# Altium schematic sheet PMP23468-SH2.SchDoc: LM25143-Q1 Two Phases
size 431 x 279 mm; Date: Not shown in title block; ApprovedBy: Not shown in title block; CheckedBy: Not shown in title block; Author: Not shown in title block; CompanyName: Not shown in title block; Engineer: Not shown in title block; Organization: Not shown in title block; Address1: Not shown in title block; Address2: Not shown in title block; Address3: Not shown in title block; Address4: Not shown in title block; DocumentNumber: 2; Revision: Use project parameter SCH_Rev; SheetNumber: 2; SheetTotal: 2; PageSetup: Record=PageOptions¦CenterHorizontal=True¦CenterVertical=True¦PrintScale=0.96¦XCorrection=1.00¦YCorrection=1.00¦PrintKind=0¦BorderSize=5000000¦LeftOffset=0¦BottomOffset=0¦Orientation=2¦PaperLength=1000¦PaperWidth=1000¦Scale=100¦PaperSource=7¦PrintQuality=600¦MediaType=1¦DitherType=10¦PaperKind=11" x 17"¦PrintScaleMode=1
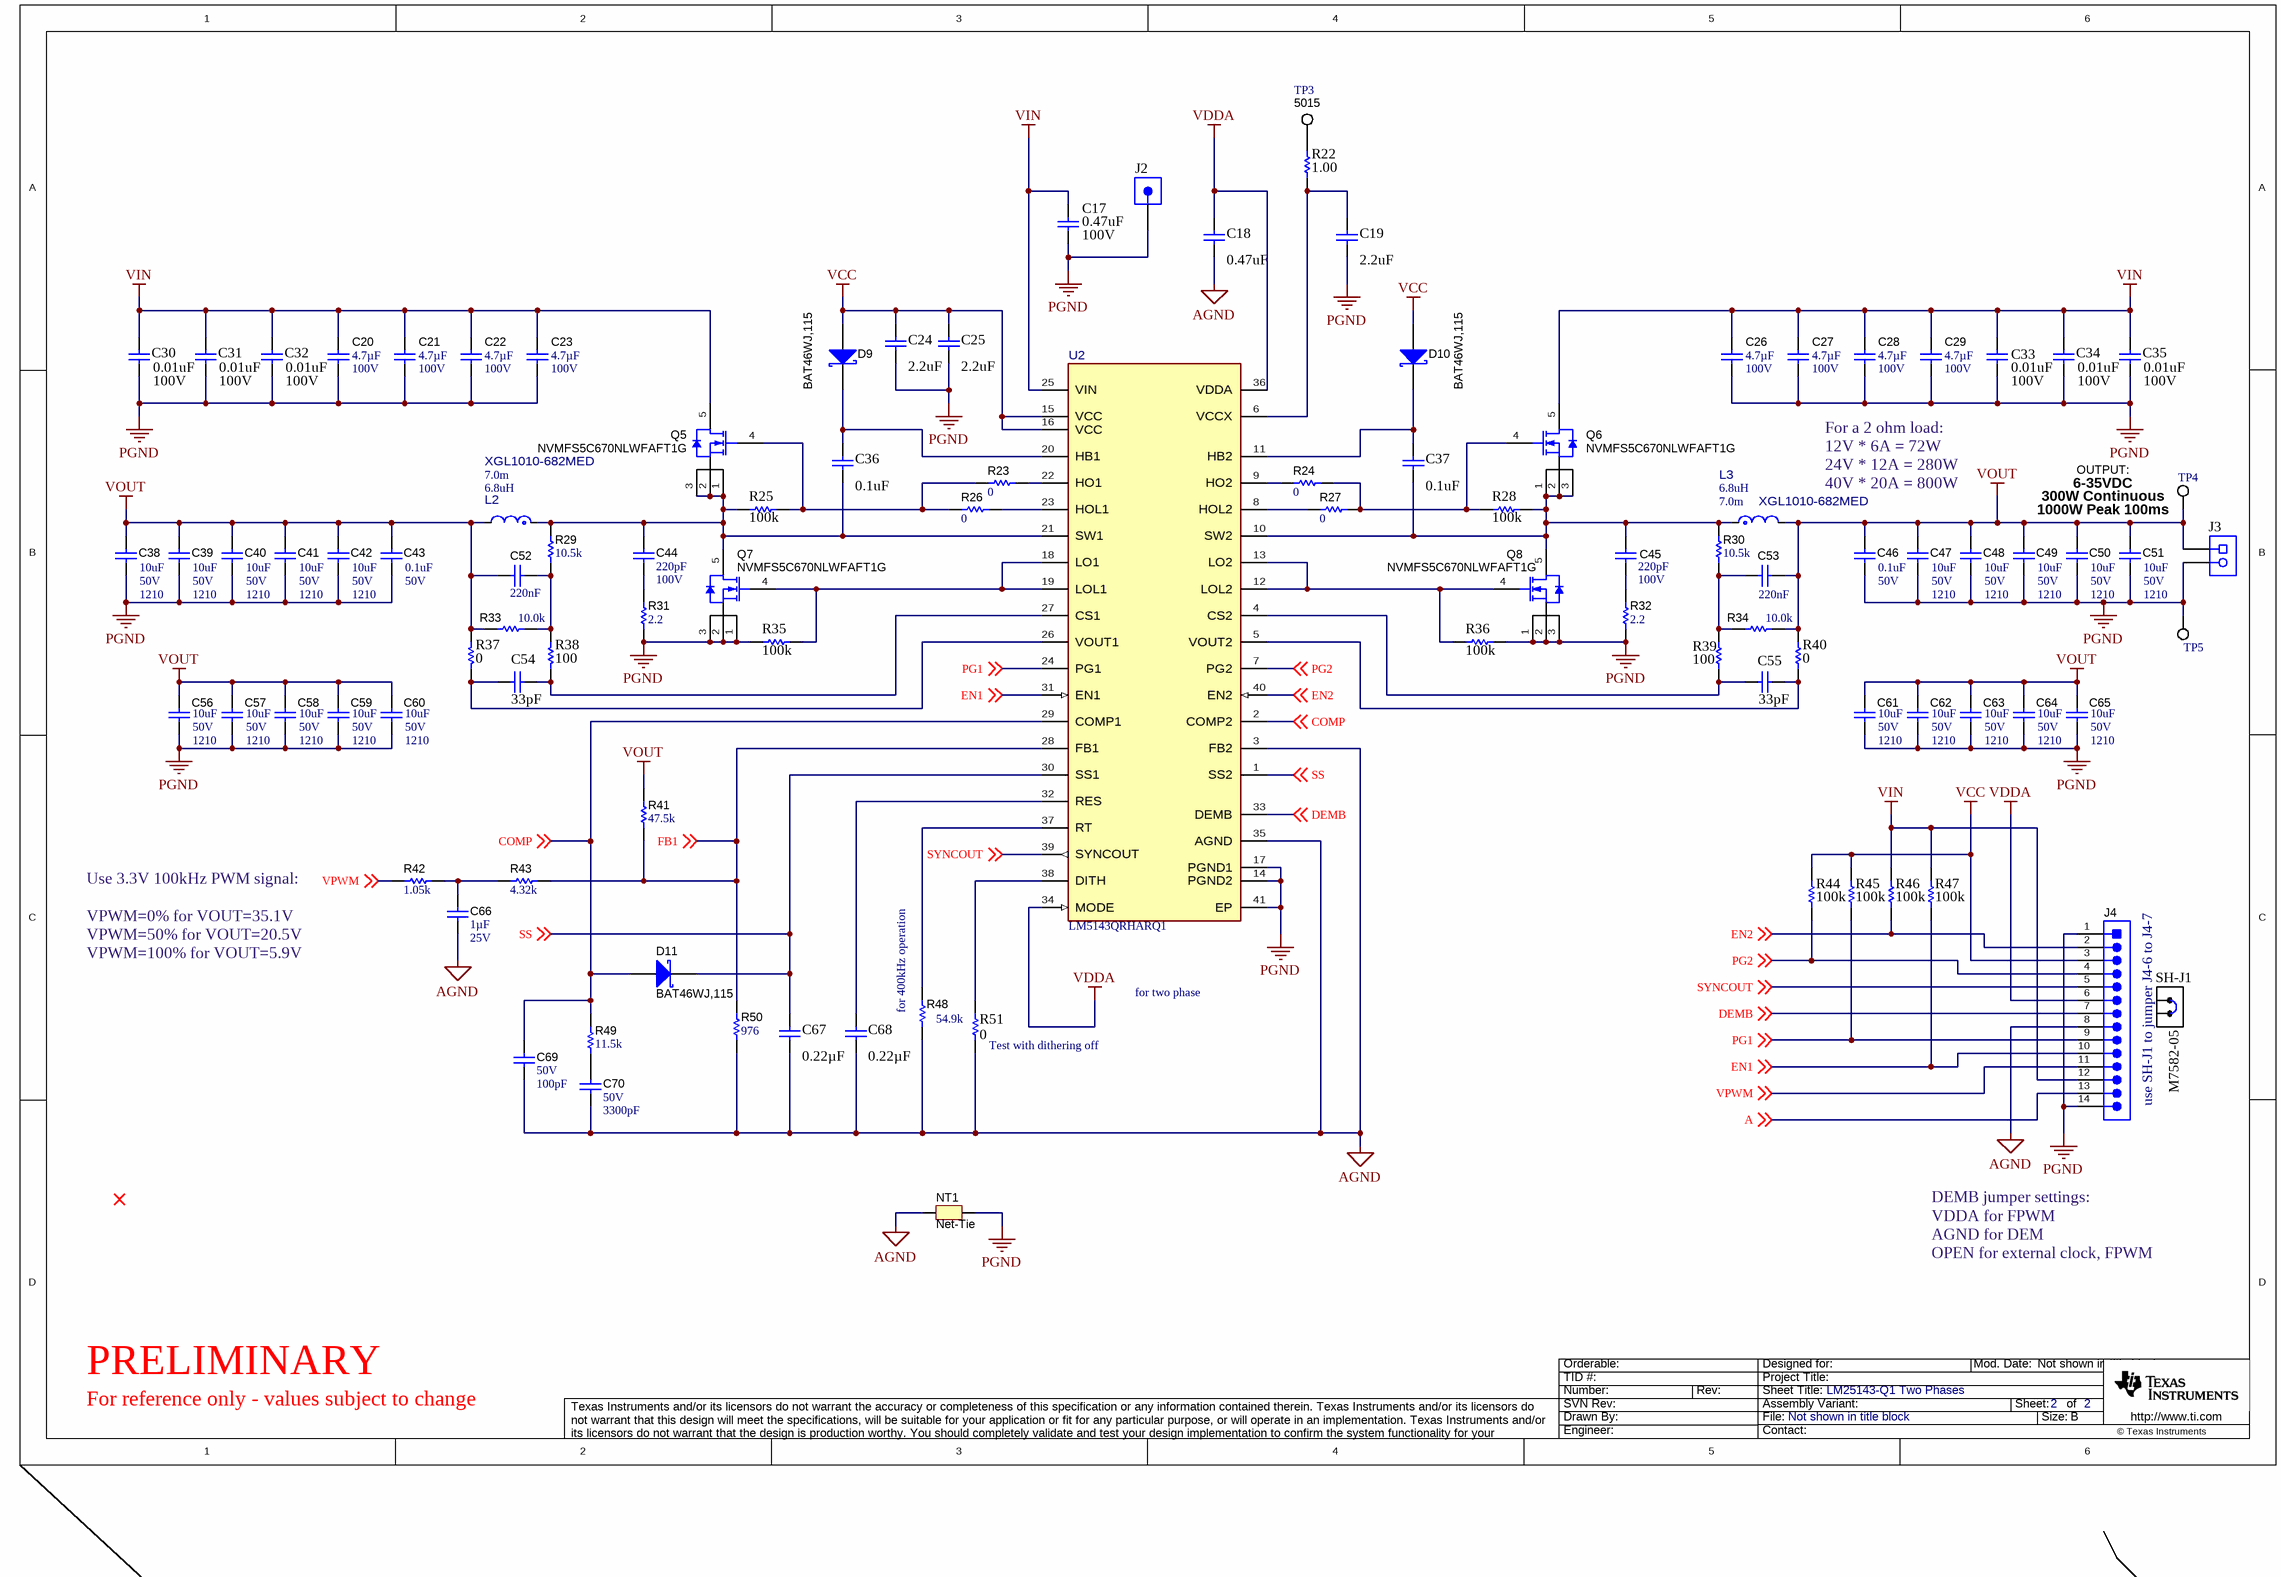
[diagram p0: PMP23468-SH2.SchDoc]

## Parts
C17  VDC_V: 100V  ValueDisplayed: 0.47uF  [0805L]  (hidden comment: GRM21BR72A474KA73L)
C18  ValueDisplayed: 0.47uF  [0603L]  (hidden comment: GCM188R71C474KA55D)
C19  ValueDisplayed: 2.2uF  [0603L]  (hidden comment: GRM188R71A225KE15D)
C20  VDC_V: 100V  ValueDisplayed: 4.7µF  [1210_220]  (hidden comment: GCM32DC72A475KE02L)
C21  VDC_V: 100V  ValueDisplayed: 4.7µF  [1210_220]  (hidden comment: GCM32DC72A475KE02L)
C22  VDC_V: 100V  ValueDisplayed: 4.7µF  [1210_220]  (hidden comment: GCM32DC72A475KE02L)
C23  VDC_V: 100V  ValueDisplayed: 4.7µF  [1210_220]  (hidden comment: GCM32DC72A475KE02L)
C24  ValueDisplayed: 2.2uF  [0603L]  (hidden comment: GRM188R71A225KE15D)
C25  ValueDisplayed: 2.2uF  [0603L]  (hidden comment: GRM188R71A225KE15D)
C26  VDC_V: 100V  ValueDisplayed: 4.7µF  [1210_220]  (hidden comment: GCM32DC72A475KE02L)
C27  VDC_V: 100V  ValueDisplayed: 4.7µF  [1210_220]  (hidden comment: GCM32DC72A475KE02L)
C28  VDC_V: 100V  ValueDisplayed: 4.7µF  [1210_220]  (hidden comment: GCM32DC72A475KE02L)
C29  VDC_V: 100V  ValueDisplayed: 4.7µF  [1210_220]  (hidden comment: GCM32DC72A475KE02L)
C30  VDC_V: 100V  ValueDisplayed: 0.01uF  [0402S]  (hidden comment: CGA2B3X7S2A103K050BB)
C31  VDC_V: 100V  ValueDisplayed: 0.01uF  [0402S]  (hidden comment: CGA2B3X7S2A103K050BB)
C32  VDC_V: 100V  ValueDisplayed: 0.01uF  [0402S]  (hidden comment: CGA2B3X7S2A103K050BB)
C33  VDC_V: 100V  ValueDisplayed: 0.01uF  [0402S]  (hidden comment: CGA2B3X7S2A103K050BB)
C34  VDC_V: 100V  ValueDisplayed: 0.01uF  [0402S]  (hidden comment: CGA2B3X7S2A103K050BB)
C35  VDC_V: 100V  ValueDisplayed: 0.01uF  [0402S]  (hidden comment: CGA2B3X7S2A103K050BB)
C36  ValueDisplayed: 0.1uF  [0603L]  (hidden comment: CGA3E2X7R1E104K080AA)
C37  ValueDisplayed: 0.1uF  [0603L]  (hidden comment: CGA3E2X7R1E104K080AA)
C38  PackageReference: 1210  VDC_V: 50V  ValueDisplayed: 10uF  [1210_270]  (hidden comment: UMJ325KB7106KMHT)
C39  PackageReference: 1210  VDC_V: 50V  ValueDisplayed: 10uF  [1210_270]  (hidden comment: UMJ325KB7106KMHT)
C40  PackageReference: 1210  VDC_V: 50V  ValueDisplayed: 10uF  [1210_270]  (hidden comment: UMJ325KB7106KMHT)
C41  PackageReference: 1210  VDC_V: 50V  ValueDisplayed: 10uF  [1210_270]  (hidden comment: UMJ325KB7106KMHT)
C42  PackageReference: 1210  VDC_V: 50V  ValueDisplayed: 10uF  [1210_270]  (hidden comment: UMJ325KB7106KMHT)
C43  Value2: 50V  ValueDisplayed: 0.1uF  [0603]  (hidden comment: CGA3E2X7R1H104K080AA)
C44  Cap_F: 220pF  VDC_V: 100V  [0603_HV]  (hidden comment: 06031C221KAT2A)
C45  Cap_F: 220pF  VDC_V: 100V  [0603_HV]  (hidden comment: 06031C221KAT2A)
C46  Value2: 50V  ValueDisplayed: 0.1uF  [0603]  (hidden comment: CGA3E2X7R1H104K080AA)
C47  PackageReference: 1210  VDC_V: 50V  ValueDisplayed: 10uF  [1210_270]  (hidden comment: UMJ325KB7106KMHT)
C48  PackageReference: 1210  VDC_V: 50V  ValueDisplayed: 10uF  [1210_270]  (hidden comment: UMJ325KB7106KMHT)
C49  PackageReference: 1210  VDC_V: 50V  ValueDisplayed: 10uF  [1210_270]  (hidden comment: UMJ325KB7106KMHT)
C50  PackageReference: 1210  VDC_V: 50V  ValueDisplayed: 10uF  [1210_270]  (hidden comment: UMJ325KB7106KMHT)
C51  PackageReference: 1210  VDC_V: 50V  ValueDisplayed: 10uF  [1210_270]  (hidden comment: UMJ325KB7106KMHT)
C52  Cap_F: 220nF  [0603]  (hidden comment: CGA3E3X7R1H224K080AB)
C53  Cap_F: 220nF  [0603]  (hidden comment: CGA3E3X7R1H224K080AB)
C54  ValueDisplayed: 33pF  [0603L]  (hidden comment: 06031A330JAT2A)
C55  ValueDisplayed: 33pF  [0603L]  (hidden comment: 06031A330JAT2A)
C56  PackageReference: 1210  VDC_V: 50V  ValueDisplayed: 10uF  [1210_270]  (hidden comment: UMJ325KB7106KMHT)
C57  PackageReference: 1210  VDC_V: 50V  ValueDisplayed: 10uF  [1210_270]  (hidden comment: UMJ325KB7106KMHT)
C58  PackageReference: 1210  VDC_V: 50V  ValueDisplayed: 10uF  [1210_270]  (hidden comment: UMJ325KB7106KMHT)
C59  PackageReference: 1210  VDC_V: 50V  ValueDisplayed: 10uF  [1210_270]  (hidden comment: UMJ325KB7106KMHT)
C60  PackageReference: 1210  VDC_V: 50V  ValueDisplayed: 10uF  [1210_270]  (hidden comment: UMJ325KB7106KMHT)
C61  PackageReference: 1210  VDC_V: 50V  ValueDisplayed: 10uF  [1210_270]  (hidden comment: UMJ325KB7106KMHT)
C62  PackageReference: 1210  VDC_V: 50V  ValueDisplayed: 10uF  [1210_270]  (hidden comment: UMJ325KB7106KMHT)
C63  PackageReference: 1210  VDC_V: 50V  ValueDisplayed: 10uF  [1210_270]  (hidden comment: UMJ325KB7106KMHT)
C64  PackageReference: 1210  VDC_V: 50V  ValueDisplayed: 10uF  [1210_270]  (hidden comment: UMJ325KB7106KMHT)
C65  PackageReference: 1210  VDC_V: 50V  ValueDisplayed: 10uF  [1210_270]  (hidden comment: UMJ325KB7106KMHT)
C66  Cap_F: 1µF  VDC_V: 25V  [0603S]  (hidden comment: CGA3E1X7R1E105K080AC)
C67  ValueDisplayed: 0.22µF  [0603L]  (hidden comment: CL10B224KO8VPNC)
C68  ValueDisplayed: 0.22µF  [0603L]  (hidden comment: CL10B224KO8VPNC)
C69  VDC_V: 50V  ValueDisplayed: 100pF  [0603]  (hidden comment: CGA3E2NP01H101J080AA)
C70  VDC_V: 50V  ValueDisplayed: 3300pF  [0603]  (hidden comment: GRM1885C1H332JA01D)
D9  BAT46WJ,115  [SOD-323F]
D10  BAT46WJ,115  [SOD-323F]
D11  BAT46WJ,115  [SOD-323F]
J2  1040  [CONN_1040]  (value not drawn)
J3  EM292902-UL  [Eaton_EM292902]  (value not drawn)
J4  TSW-114-07-G-S  [TSW-114-07-G-S]  (value not drawn)
L2  XGL1010-682MED  value 6.8uH  DCR_ohm: 7.0m  [FP-XGL1010-103MED_SMT_IND_10MM0_11MM3-MFG]
L3  XGL1010-682MED  value 6.8uH  DCR_ohm: 7.0m  [FP-XGL1010-103MED_SMT_IND_10MM0_11MM3-MFG]
NT1  Net-Tie  [Net-Tie_10mil]  (net tie, no BOM)
Q5  NVMFS5C670NLWFAFT1G  [SO-8FL]
Q6  NVMFS5C670NLWFAFT1G  [SO-8FL]
Q7  NVMFS5C670NLWFAFT1G  [SO-8FL]
Q8  NVMFS5C670NLWFAFT1G  [SO-8FL]
R22  ValueDisplayed: 1.00  [0603L]  (hidden comment: RC0603FR-071RL)
R23  ValueDisplayed: 0  [0402L]  (hidden comment: ERJ-2GE0R00X)
R24  ValueDisplayed: 0  [0402L]  (hidden comment: ERJ-2GE0R00X)
R25  ValueDisplayed: 100k  [0603L]  (hidden comment: CRCW0603100KFKEA)
R26  ValueDisplayed: 0  [0402L]  (hidden comment: ERJ-2GE0R00X)
R27  ValueDisplayed: 0  [0402L]  (hidden comment: ERJ-2GE0R00X)
R28  ValueDisplayed: 100k  [0603L]  (hidden comment: CRCW0603100KFKEA)
R29  ValueDisplayed: 10.5k  [0603]  (hidden comment: CRCW060310K5FKEA)
R30  ValueDisplayed: 10.5k  [0603]  (hidden comment: CRCW060310K5FKEA)
R31  ValueDisplayed: 2.2  [0805_HV]  (hidden comment: ERJ-6GEYJ2R2V)
R32  ValueDisplayed: 2.2  [0805_HV]  (hidden comment: ERJ-6GEYJ2R2V)
R33  ValueDisplayed: 10.0k  [0603]  (hidden comment: RMCF0603FT10K0)
R34  ValueDisplayed: 10.0k  [0603]  (hidden comment: RMCF0603FT10K0)
R35  ValueDisplayed: 100k  [0603L]  (hidden comment: CRCW0603100KFKEA)
R36  ValueDisplayed: 100k  [0603L]  (hidden comment: CRCW0603100KFKEA)
R37  ValueDisplayed: 0  [0603L]  (hidden comment: CRCW06030000Z0EA)
R38  ValueDisplayed: 100  [0603L]  (hidden comment: CRCW0603100RFKEA)
R39  ValueDisplayed: 100  [0603L]  (hidden comment: CRCW0603100RFKEA)
R40  ValueDisplayed: 0  [0603L]  (hidden comment: CRCW06030000Z0EA)
R41  ValueDisplayed: 47.5k  [0603L]  (hidden comment: CRCW060347K5FKEA)
R42  ValueDisplayed: 1.05k  [0603L]  (hidden comment: CRCW06031K05FKEA)
R43  ValueDisplayed: 4.32k  [0603L]  (hidden comment: CRCW06034K32FKEA)
R44  ValueDisplayed: 100k  [0603L]  (hidden comment: CRCW0603100KFKEA)
R45  ValueDisplayed: 100k  [0603L]  (hidden comment: CRCW0603100KFKEA)
R46  ValueDisplayed: 100k  [0603L]  (hidden comment: CRCW0603100KFKEA)
R47  ValueDisplayed: 100k  [0603L]  (hidden comment: CRCW0603100KFKEA)
R48  ValueDisplayed: 54.9k  [0603L]  (hidden comment: CRCW060354K9FKEA)
R49  ValueDisplayed: 11.5k  [0603]  (hidden comment: CRCW060311K5FKEA)
R50  ValueDisplayed: 976  [0603]  (hidden comment: CRCW0603976RFKEA)
R51  ValueDisplayed: 0  [0603L]  (hidden comment: CRCW06030000Z0EA)
SH-J1  M7582-05  [Harwin_M7582-05]
TP3  5015  [Testpoint_Keystone_Miniature]
TP4  5015  [Testpoint_Keystone_Miniature]  (value not drawn)
TP5  5015  [Testpoint_Keystone_Miniature]  (value not drawn)
U2  LM5143QRHARQ1  [RHA0040N-MFG]

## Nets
AGND: C18.1 C66.1 C67.2 C68.2 C69.2 C70.2 J4.8 NT1.1 R48.1 R50.1 R51.2 U2.3(FB2) U2.35(AGND)
PGND: C17.1 C19.2 C20.2 C21.2 C22.2 C23.2 C24.2 C25.2 C26.2 C27.2 C28.2 C29.2 C30.2 C31.2 C32.2 C33.2 C34.2 C35.2 C38.2 C39.2 C40.2 C41.2 C42.2 C43.2 C46.2 C47.2 C48.2 C49.2 C50.2 C51.2 C56.2 C57.2 C58.2 C59.2 C60.2 C61.2 C62.2 C63.2 C64.2 C65.2 J2.1 J3.2 J4.1 J4.14 NT1.2 Q7.1(S) Q7.2(S) Q7.3(S) Q8.1(S) Q8.2(S) Q8.3(S) R31.1 R32.1 R35.2 R36.1 TP5.1 U2.14(PGND2) U2.17(PGND1) U2.41(EP)
VCC: C24.1 C25.1 D9.2(A) D10.2(A) J4.3 R44.2 R45.2 U2.15(VCC) U2.16(VCC)
VDDA: C18.2 J4.6 U2.34(MODE) U2.36(VDDA)
VIN: C17.2 C20.1 C21.1 C22.1 C23.1 C26.1 C27.1 C28.1 C29.1 C30.1 C31.1 C32.1 C33.1 C34.1 C35.1 J4.12 Q5.5(D) Q6.5(D) R46.2 R47.2 U2.25(VIN)
VOUT: C38.1 C39.1 C40.1 C41.1 C42.1 C43.1 C46.1 C47.1 C48.1 C49.1 C50.1 C51.1 C52.2 C53.1 C56.1 C57.1 C58.1 C59.1 C60.1 C61.1 C62.1 C63.1 C64.1 C65.1 J3.1 L2.2 L3.2 R33.1 R34.2 R37.2 R40.2 R41.2 TP4.1
A: J4.13 ; off-sheet A
COMP: C69.1 D11.2(A) R49.2 U2.2(COMP2) U2.29(COMP1) ; off-sheet COMP
DEMB: J4.7 U2.33(DEMB) ; off-sheet DEMB
EN1: J4.10 R47.1 U2.31(EN1) ; off-sheet EN1
EN2: J4.2 R46.1 U2.40(EN2) ; off-sheet EN2
FB1: R41.1 R43.1 R50.2 U2.28(FB1) ; off-sheet FB1
PG1: J4.9 R45.1 U2.24(PG1) ; off-sheet PG1
PG2: J4.4 R44.1 U2.7(PG2) ; off-sheet PG2
SS: C67.1 D11.1(K) U2.1(SS2) U2.30(SS1) ; off-sheet SS
SYNCOUT: J4.5 U2.39(SYNCOUT) ; off-sheet SYNCOUT
VPWM: J4.11 R42.2 ; off-sheet VPWM
NetC19_1: C19.1 R22.1 U2.6(VCCX)
NetC36_1: C36.1 C44.1 L2.1 Q5.1(S) Q5.2(S) Q5.3(S) Q7.5(D) R25.2 R29.2 U2.21(SW1)
NetC36_2: C36.2 D9.1(K) U2.20(HB1)
NetC37_1: C37.1 C45.1 L3.1 Q6.1(S) Q6.2(S) Q6.3(S) Q8.5(D) R28.1 R30.1 U2.10(SW2)
NetC37_2: C37.2 D10.1(K) U2.11(HB2)
NetC44_2: C44.2 R31.2
NetC45_2: C45.2 R32.2
NetC52_1: C52.1 R29.1 R33.2 R38.2
NetC53_2: C53.2 R30.2 R34.1 R39.2
NetC54_1: C54.1 R37.1 U2.26(VOUT1)
NetC54_2: C54.2 R38.1 U2.27(CS1)
NetC55_1: C55.1 R40.1 U2.5(VOUT2)
NetC55_2: C55.2 R39.1 U2.4(CS2)
NetC66_2: C66.2 R42.1 R43.2
NetC68_1: C68.1 U2.32(RES)
NetC70_1: C70.1 R49.1
NetQ5_4: Q5.4(G) R23.1 R25.1 R26.1
NetQ6_4: Q6.4(G) R24.2 R27.2 R28.2
NetQ7_4: Q7.4(G) R35.1 U2.18(LO1) U2.19(LOL1)
NetQ8_4: Q8.4(G) R36.2 U2.12(LOL2) U2.13(LO2)
NetR22_2: R22.2 TP3.1
NetR23_2: R23.2 U2.22(HO1)
NetR24_1: R24.1 U2.9(HO2)
NetR26_2: R26.2 U2.23(HOL1)
NetR27_1: R27.1 U2.8(HOL2)
NetR48_2: R48.2 U2.37(RT)
NetR51_1: R51.1 U2.38(DITH)

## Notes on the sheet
- For a 2 ohm load:
  12V * 6A = 72W
  24V * 12A = 280W
  40V * 20A = 800W
- 6-35VDC
- (near TP4) 300W Continuous
- OUTPUT:
- 1000W Peak 100ms
- Use 3.3V 100kHz PWM signal:
  VPWM=0% for VOUT=35.1V
  VPWM=50% for VOUT=20.5V
  VPWM=100% for VOUT=5.9V
- (near R48) for 400kHz operation
- for two phase
- (near R51) Test with dithering off
- (near SH-J1) use SH-J1 to jumper J4-6 to J4-7
- DEMB jumper settings:
  VDDA for FPWM
  AGND for DEM
  OPEN for external clock, FPWM
- PRELIMINARY
- For reference only - values subject to change

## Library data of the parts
C17 = CMP-0008374-2: CAP, CERM, 0.47 uF, 100 V, +/- 10%, X7R, 0805; Manufacturer: MuRata; TaMin_C: -55°C; Polarized: N; SizeAreaWB_mm2: 6.75; Value1: Unknown; U/M: EA; Value: 0.47uF; TaMax_C: 125°C; SizeZ_mm: 1.45; SizeX_mm: 2; SizeY_mm: 1.25; Cap_Case: 0805; SizeArea_mm2: 2.5; CompType: Capacitor; Cap_F: 470nF; AEC Category: Q200
C18 = CMP-0007138-4: CAP, CERM, 0.47 uF, 16 V, +/- 10%, X7R, AEC-Q200 Grade 1, 0603; Manufacturer: MuRata; TaMin_C: -55°C; Polarized: N; SizeAreaWB_mm2: 4.68; Value1: Unknown; U/M: EA; Value: 0.47uF; TaMax_C: 125°C; SizeZ_mm: 1; SizeX_mm: 1.6; SizeY_mm: 0.8; Cap_Case: 0603; Value2: 16V; SizeArea_mm2: 1.28; CompType: Capacitor; AEC Qualified: Y; Cap_F: 470nF; AEC Category: Q200
C19 = CMP-0007370-4: CAP, CERM, 2.2 uF, 10 V, +/- 10%, X7R, 0603; Manufacturer: MuRata; TaMin_C: -55°C; Polarized: N; SizeAreaWB_mm2: 4.68; Value1: 0.009 ohm; U/M: EA; Value: 2.2uF; TaMax_C: 125°C; SizeZ_mm: 1; SizeX_mm: 1.6; SizeY_mm: 0.8; Cap_Case: 0603; Value2: 10V; SizeArea_mm2: 1.28; CompType: Capacitor; Cap_F: 2.2µF; AEC Category: Q200; ESR_ohm: 9m
C20-C23 C26-C29 = CMP-0082268-1: CAP, CERM, 4.7 µF, 100 V,+/- 10%, X7S, AEC-Q200 Grade 1, 1210; Manufacturer: MuRata; TaMin_C: -55°C; ESR_ohm: 1m; Polarized: N; SizeAreaWB_mm2: 14.7; Value1: 0.001 ohm; U/M: EA; Value: 4.7uF; TaMax_C: 125°C; SizeZ_mm: 2.2; SizeX_mm: 3.2; SizeY_mm: 2.5; Cap_Case: 1210; SizeArea_mm2: 8; AEC Qualified: Y; IRMS_A: 6A; AEC Grade: 1; AEC Category: Q200
C24 C25 = CMP-0007370-4: CAP, CERM, 2.2 uF, 10 V, +/- 10%, X7R, 0603; Manufacturer: MuRata; TaMin_C: -55°C; ESR_ohm: 9m; Polarized: N; SizeAreaWB_mm2: 4.68; Value1: 0.009 ohm; U/M: EA; Value: 2.2uF; TaMax_C: 125°C; SizeZ_mm: 1; SizeX_mm: 1.6; SizeY_mm: 0.8; Cap_Case: 0603; Value2: 10V; SizeArea_mm2: 1.28; CompType: Capacitor; Cap_F: 2.2µF; AEC Category: Q200
C30-C35 = CMP-0006333-2: CAP, CERM, 0.01 uF, 100 V, +/- 10%, X7S, AEC-Q200 Grade 1, 0402; Manufacturer: TDK; TaMin_C: -55°C; ESR_ohm: 0.4102; Polarized: N; SizeAreaWB_mm2: 3; Value1: 0.410191 ohm; U/M: EA; Value: 0.01uF; TaMax_C: 125°C; SizeZ_mm: 0.6; SizeX_mm: 1; SizeY_mm: 0.5; Cap_Case: 0402; AEC Qualified: Y; Cap_F: 10nF; IRMS_A: 291.729mA; AEC Category: Q200
C36 C37 = CMP-0007077-5: CAP, CERM, 0.1 uF, 25 V, +/- 10%, X7R, AEC-Q200 Grade 1, 0603; Manufacturer: TDK; TaMin_C: -55°C; Polarized: N; SizeAreaWB_mm2: 4.68; Value1: Unknown; U/M: EA; Value: 0.1uF; TaMax_C: 125°C; SizeZ_mm: 1; SizeX_mm: 1.6; SizeY_mm: 0.8; Cap_Case: 0603; Value2: 25V; SizeArea_mm2: 1.28; AEC Qualified: Y; Cap_F: 100nF; AEC Category: Q200
C38-C42 C47-C51 C56-C65 = CMP-0009257-2: CAP, CERM, 10 uF, 50 V, +/- 10%, X7R, AEC-Q200 Grade 1, 1210; Manufacturer: Taiyo Yuden; TaMin_C: -55°C; Polarized: N; SizeAreaWB_mm2: 14.7; Value1: Unknown; Value: 10uF; TaMax_C: 125°C; SizeZ_mm: 2.7; SizeX_mm: 3.2; SizeY_mm: 2.5; SizeArea_mm2: 8; AEC Qualified: Y; Cap_F: 10µF; AEC Grade: 1; AEC Category: Q200; U/M: EA
C43 C46 = CMP-0007078-4: CAP, CERM, 0.1 uF, 50 V, +/- 10%, X7R, AEC-Q200 Grade 1, 0603; Manufacturer: TDK; TaMin_C: -55°C; Polarized: N; SizeAreaWB_mm2: 4.68; Value1: 0.0296 ohm; U/M: EA; Value: 0.1uF; TaMax_C: 125°C; SizeZ_mm: 1; SizeX_mm: 1.6; SizeY_mm: 0.8; SizeArea_mm2: 1.28; AEC Qualified: Y; Cap_F: 100nF; AEC Category: Q200; ESR_ohm: 29.6m; IRMS_A: 971.99mA
C44 C45 = CMP-0006735-5: CAP, CERM, 220 pF, 100 V, +/- 10%, X7R, 0603; Manufacturer: AVX; TaMin_C: -55°C; ESR_ohm: 0.579; Polarized: N; SizeAreaWB_mm2: 4.68; Value1: 0.579 ohm; U/M: EA; Value: 220pF; TaMax_C: 125°C; SizeZ_mm: 1; SizeX_mm: 1.6; SizeY_mm: 0.8; Cap_Case: 0603; SizeArea_mm2: 1.28; AEC Category: Q200
C52 C53 = CMP-0007094-5: CAP, CERM, 0.22 uF, 50 V, +/- 10%, X7R, AEC-Q200 Grade 1, 0603; Manufacturer: TDK; TaMin_C: -55°C; ESR_ohm: 21.699m; Polarized: N; SizeAreaWB_mm2: 4.68; Value1: 0.021699 ohm; U/M: EA; Value: 0.22uF; TaMax_C: 125°C; SizeZ_mm: 1; SizeX_mm: 1.6; SizeY_mm: 0.8; Value2: 50V; SizeArea_mm2: 1.28; AEC Qualified: Y; IRMS_A: 1.125A; AEC Category: Q200
C54 C55 = CMP-0006722-4: CAP, CERM, 33 pF, 100 V, +/- 5%, C0G/NP0, 0603; Manufacturer: AVX; TaMin_C: -55°C; ESR_ohm: 2.09d; Polarized: N; SizeAreaWB_mm2: 4.68; Value1: 0.209 ohm; U/M: EA; Value: 33pF; TaMax_C: 125°C; SizeZ_mm: 1; SizeX_mm: 1.6; SizeY_mm: 0.8; Cap_Case: 0603; Value2: 100V; SizeArea_mm2: 1.28; CompType: Capacitor; AEC Category: Q200
C66 = CMP-0076705-3: CAP, CERM, 1 µF, 25 V,+/- 10%, X7R, AEC-Q200 Grade 1, 0603; Manufacturer: TDK; SizeAreaWB_mm2: 4.68; SizeArea_mm2: 1.28; AEC Qualified: Y; AEC Category: Q200; Value: 1uF; TaMax_C: 125°C; SizeZ_mm: 1.0; AEC Grade: 1; Polarized: N; TaMin_C: -55°C; SizeY_mm: 0.8; U/M: EA; SizeX_mm: 1.6; Cap_Case: 1.6x0.8x0.8mm
C67 C68 = CMP-0080102-1: CAP, CERM, 0.22 µF, 16 V,+/- 10%, X7R, AEC-Q200 Grade 1, 0603; Manufacturer: Samsung; TaMin_C: -55°C; Polarized: N; SizeAreaWB_mm2: 4.68; U/M: EA; Value: 0.22uF; TaMax_C: 125°C; SizeZ_mm: 1; SizeX_mm: 1.6; SizeY_mm: 0.8; Cap_Case: 0603; Value2: 16V; SizeArea_mm2: 1.28; CompType: Capacitor; AEC Qualified: Y; Cap_F: 220nF; AEC Category: Q200
C69 = CMP-0007075-4: CAP, CERM, 100 pF, 50 V, +/- 5%, C0G/NP0, AEC-Q200 Grade 0, 0603; Manufacturer: TDK; TaMin_C: -55°C; Polarized: N; SizeAreaWB_mm2: 4.68; Value1: Unknown; U/M: EA; Value: 100pF; TaMax_C: 150°C; SizeZ_mm: 1; SizeX_mm: 1.6; SizeY_mm: 0.8; SizeArea_mm2: 1.28; AEC Qualified: Y; AEC Grade: 0; AEC Category: Q200
C70 = CMP-0007210-4: CAP, CERM, 3300 pF, 50 V, +/- 5%, C0G/NP0, 0603; Manufacturer: MuRata; TaMin_C: -55°C; Polarized: N; SizeAreaWB_mm2: 4.68; Value1: Unknown; U/M: EA; Value: 3300pF; TaMax_C: 125°C; SizeZ_mm: 1; SizeX_mm: 1.6; SizeY_mm: 0.8; SizeArea_mm2: 1.28; Cap_F: 3.3nF; AEC Category: Q200
D9-D11 = CMP-0076946-2: Diode, Schottky, 100 V, 0.25 A, SOD-323F; Manufacturer: Nexperia; SizeAreaWB_mm2: 7.875; Value2: 0.85V; SizeX_mm: 2.5; Green_REACh: Incomplete; SizeArea_mm2: 3.125; Vf_V: 850mV; Green_Lifecycle: Not Set; Vr_V: 100V; TJmax_C: 150°C; Value1: 0.25A; Io_A: 250mA; SizeZ_mm: 0.8; Value: 100V; AEC Category: Q101; SizeY_mm: 1.25
J2 = CMP-0055161-1: TEST POINT SLOTTED .118", TH; Manufacturer: Keystone; CNHeader: FALSE; Green_Lifecycle: Active; Green_REACh: Passed; CT: TRUE
J3 = CMP-0077513-2: Terminal Block, 10.16mm, 2x1, Tin, R/A, TH; Manufacturer: Eaton; Pitch_mm: 10.16; Gender: Female; Voltage_V: 300V; Current_A: 65A; Cert_CULUS: Y; Row_Count: 1
J4 = CMP-0075428-1: Header, 100mil, 14x1, Gold, TH; Manufacturer: Samtec; Pitch_mm: 2.54; Cert_VDE: N; Gender: Male; Cert_CSA: Y; Current_A: 6.3A; Voltage_V: 550V; CT: False; Row_Count: 1; CNHeader: True; Green_Lifecycle: Active; Green_REACh: Passed
L2 L3 = CMP-0120510-1: 6.8 µH Shielded Molded Inductor 21.2 A 7.0mOhm Max Nonstandard; Manufacturer: Coilcraft; PartNumber: XGL1010-103MED; AEC Grade: Grade 1; AEC Qualified: Yes; Ind_H: 10µH; Irms: 18.2A; Isat: 8.3A; Material: Composite; SizeZ_mm: 10mm; Self Resonant Frequency: 12MHz; Shrouded: true; TaMax_C: +125°C; TaMin_C: -40°C; Test Frequency: 1MHz; Tolerance_%: 20%
NT1 = CMP-0078142-6: Single point connection between nets.
Q5 Q6 = CMP-0750168-1: MOSFET, N-CH, 60 V, 17 A, AEC-Q101, SO-8FL; Manufacturer: ON Semiconductor; Alternate Manufacturer: None; IdsMax_A: 17A; VdsMax_V: 60V; QgTyp_nC: 20; AEC Qualified: Y; Rdson45_ohm: 8.8m; Vgs_V: 20V; SizeZ_mm: 1.1; ChMode: Enhancement; SizeAreaWB_mm2: 58.2725; Value1: 0.0088 ohm; ChType: N; SizeArea_mm2: 31.6725; SizeX_mm: 6.15; SizeY_mm: 5.15; Value2: 20 nC; AEC Category: Q101; Value: 60V
Q7 Q8 = CMP-0750168-1: MOSFET, N-CH, 60 V, 17 A, AEC-Q101, SO-8FL; Manufacturer: ON Semiconductor; Alternate Manufacturer: None; AEC Qualified: Y; IdsMax_A: 17A; QgTyp_nC: 20; Rdson45_ohm: 8.8m; SizeZ_mm: 1.1; VdsMax_V: 60V; Vgs_V: 20V; ChMode: Enhancement; SizeAreaWB_mm2: 58.2725; Value1: 0.0088 ohm; ChType: N; SizeArea_mm2: 31.6725; SizeX_mm: 6.15; SizeY_mm: 5.15; Value2: 20 nC; AEC Category: Q101; Value: 60V
R22 = CMP-0022900-4: RES, 1.00, 1%, 0.1 W, 0603; Manufacturer: Yageo; Power_W: 100mW; TempCo: 200 ppm/C; Value_Code: 1R00; Value: 1.00; EIA_Code: E96; Res_ohm: 1; SizeX_mm: 1.6; SizeY_mm: 0.8; Value2: 0.1W; SizeArea_mm2: 1.28; CompType: Resistor; AEC Qualified: N; VDC_V: 75V; AEC Category: Q200; SizeAreaWB_mm2: 4.68
R23 R24 R26 R27 = CMP-0026992-3: RES, 0, 5%, 0.1 W, AEC-Q200 Grade 0, 0402; Manufacturer: Panasonic; Power_W: 100mW; TempCo: 600 ppm/C; Value_Code: 0000; Value: 0; EIA_Code: E24; SizeX_mm: 1; SizeY_mm: 0.5; SizeZ_mm: 0.6; Value2: 0.1W; AEC Qualified: Y; VDC_V: 50V; AEC Category: Q200; SizeAreaWB_mm2: 3
R25 R28 R35 R36 R44-R47 = CMP-0021990-4: RES, 100 k, 1%, 0.1 W, AEC-Q200 Grade 0, 0603; Manufacturer: Vishay-Dale; Power_W: 100mW; TempCo: 100 ppm/C; Value: 100k; EIA_Code: E96; SizeX_mm: 1.6; SizeY_mm: 0.8; SizeZ_mm: 1; Value2: 0.1W; SizeArea_mm2: 1.28; CompType: Resistor; AEC Qualified: Y; VDC_V: 75V; AEC Category: Q200; AEC Grade: 0
R29 R30 = CMP-0022000-4: RES, 10.5 k, 1%, 0.1 W, AEC-Q200 Grade 0, 0603; Manufacturer: Vishay-Dale; Power_W: 100mW; TempCo: 100 ppm/C; Value_Code: 10k5; Value: 10.5k; EIA_Code: E96; SizeX_mm: 1.6; SizeY_mm: 0.8; SizeZ_mm: 1; Value2: 0.1W; SizeArea_mm2: 1.28; AEC Qualified: Y; VDC_V: 75V; AEC Category: Q200; AEC Grade: 0
R31 R32 = CMP-0020693-3: RES, 2.2, 5%, 0.125 W, AEC-Q200 Grade 0, 0805; Manufacturer: Panasonic; Power_W: 125mW; TempCo: 600 ppm/C; Value_Code: 2R20; Value: 2.2; EIA_Code: E24; SizeX_mm: 2; SizeY_mm: 1.25; SizeZ_mm: 1.45; Value2: 0.125W; SizeArea_mm2: 2.5; AEC Qualified: Y; VDC_V: 150V; AEC Category: Q200; AEC Grade: 0; SizeAreaWB_mm2: 6.75
R33 R34 = CMP-0023341-3: RES, 10.0 k, 1%, 0.1 W, AEC-Q200 Grade 0, 0603; Manufacturer: Stackpole Electronics Inc; Power_W: 100mW; TempCo: 100 ppm/C; Value_Code: 10k0; U/M: EA; Value: 10.0k; EIA_Code: E96; Res_ohm: 10k; SizeX_mm: 1.6; SizeY_mm: 0.8; SizeZ_mm: 1; Value2: 0.1W; SizeArea_mm2: 1.28; AEC Qualified: Y; VDC_V: 75V; AEC Grade: 0; AEC Category: Q200
R37 R40 = CMP-0025697-4: RES, 0, 5%, 0.1 W, AEC-Q200 Grade 0, 0603; Manufacturer: Vishay-Dale; Power_W: 100mW; TempCo: 200 ppm/C; Value_Code: 0000; Value: 0; EIA_Code: E24; SizeX_mm: 1.6; SizeY_mm: 0.8; SizeZ_mm: 1; Value2: 0.1W; SizeArea_mm2: 1.28; CompType: Resistor; AEC Qualified: Y; VDC_V: 75V; AEC Category: Q200
R38 R39 = CMP-0021991-4: RES, 100, 1%, 0.1 W, AEC-Q200 Grade 0, 0603; Manufacturer: Vishay-Dale; Power_W: 100mW; TempCo: 100 ppm/C; Value_Code: 100R; Value: 100; EIA_Code: E96; SizeX_mm: 1.6; SizeY_mm: 0.8; SizeZ_mm: 1; Value2: 0.1W; SizeArea_mm2: 1.28; AEC Qualified: Y; VDC_V: 75V; AEC Category: Q200; AEC Grade: 0
R41 = CMP-0022439-4: RES, 47.5 k, 1%, 0.1 W, AEC-Q200 Grade 0, 0603; Manufacturer: Vishay-Dale; Power_W: 100mW; TempCo: 100 ppm/C; Value_Code: 47k5; Value: 47.5k; EIA_Code: E96; SizeX_mm: 1.6; SizeY_mm: 0.8; SizeZ_mm: 1; Value2: 0.1W; SizeArea_mm2: 1.28; AEC Qualified: Y; VDC_V: 75V; AEC Category: Q200; AEC Grade: 0
R42 = CMP-0022111-4: RES, 1.05 k, 1%, 0.1 W, AEC-Q200 Grade 0, 0603; Manufacturer: Vishay-Dale; Power_W: 100mW; TempCo: 100 ppm/C; Value_Code: 1k05; Value: 1.05k; EIA_Code: E96; SizeX_mm: 1.6; SizeY_mm: 0.8; SizeZ_mm: 1; Value2: 0.1W; SizeArea_mm2: 1.28; AEC Qualified: Y; VDC_V: 75V; AEC Category: Q200; AEC Grade: 0
R43 = CMP-0022452-4: RES, 4.32 k, 1%, 0.1 W, AEC-Q200 Grade 0, 0603; Manufacturer: Vishay-Dale; Power_W: 100mW; TempCo: 100 ppm/C; Value_Code: 4k32; Value: 4.32k; EIA_Code: E96; SizeX_mm: 1.6; SizeY_mm: 0.8; SizeZ_mm: 1; Value2: 0.1W; SizeArea_mm2: 1.28; AEC Qualified: Y; VDC_V: 75V; AEC Category: Q200; AEC Grade: 0
R48 = CMP-0022494-4: RES, 54.9 k, 1%, 0.1 W, AEC-Q200 Grade 0, 0603; Manufacturer: Vishay-Dale; Power_W: 100mW; TempCo: 100 ppm/C; Value_Code: 54k9; Value: 54.9k; EIA_Code: E96; SizeX_mm: 1.6; SizeY_mm: 0.8; SizeZ_mm: 1; Value2: 0.1W; SizeArea_mm2: 1.28; AEC Qualified: Y; VDC_V: 75V; AEC Category: Q200; AEC Grade: 0
R49 = CMP-0022018-4: RES, 11.5 k, 1%, 0.1 W, AEC-Q200 Grade 0, 0603; Manufacturer: Vishay-Dale; Power_W: 100mW; TempCo: 100 ppm/C; Value_Code: 11k5; Value: 11.5k; EIA_Code: E96; SizeX_mm: 1.6; SizeY_mm: 0.8; SizeZ_mm: 1; Value2: 0.1W; SizeArea_mm2: 1.28; AEC Qualified: Y; VDC_V: 75V; AEC Category: Q200; AEC Grade: 0
R50 = CMP-0022662-5: RES, 976, 1%, 0.1 W, AEC-Q200 Grade 0, 0603; Manufacturer: Vishay-Dale; Power_W: 100mW; TempCo: 100 ppm/C; Value_Code: 976R; Value: 976; EIA_Code: E96; SizeX_mm: 1.6; SizeY_mm: 0.8; SizeZ_mm: 1; Value2: 0.1W; SizeArea_mm2: 1.28; AEC Qualified: Y; VDC_V: 75V; AEC Category: Q200; AEC Grade: 0
R51 = CMP-0025697-4: RES, 0, 5%, 0.1 W, AEC-Q200 Grade 0, 0603; Manufacturer: Vishay-Dale; Power_W: 100mW; TempCo: 200 ppm/C; Value_Code: 0000; Value: 0; EIA_Code: E24; SizeX_mm: 1.6; SizeY_mm: 0.8; SizeZ_mm: 1; Value2: 0.1W; SizeArea_mm2: 1.28; AEC Qualified: Y; VDC_V: 75V; AEC Category: Q200
SH-J1 = CMP-0078738-1: Single Operation 2.54mm Pitch Open Top Jumper Socket; Manufacturer: Harwin; CompType: Shunt
TP3-TP5 = CMP-0055152-2: Test Point, Miniature, SMT; Manufacturer: Keystone Electronics; CNHeader: FALSE; Green_Lifecycle: Active; Green_REACh: Passed; CT: TRUE
U2 = CMP-0094639-1: Automotive 3.5-V to 65-V Dual Synchronous Buck Controller With Low IQ; Manufacturer: Texas Instruments; TaMin_C: -40°C; SizeZ_mm: 1mm; Switching Frequency: 0.1-2.2MHz; Standoff Height: 0mm; Number Of Outputs: 2; AEC Grade: Grade 1; Output Type: Fixed,AdjustableProgrammable; TJmax_C: +150°C; Min Supply Voltage: 3.5V; AEC Qualified: Yes; Nominal Supply Current: 15-25uA; TaMax_C: +125°C; Output Voltage: 0.6-55V; Max Supply Voltage: 65V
